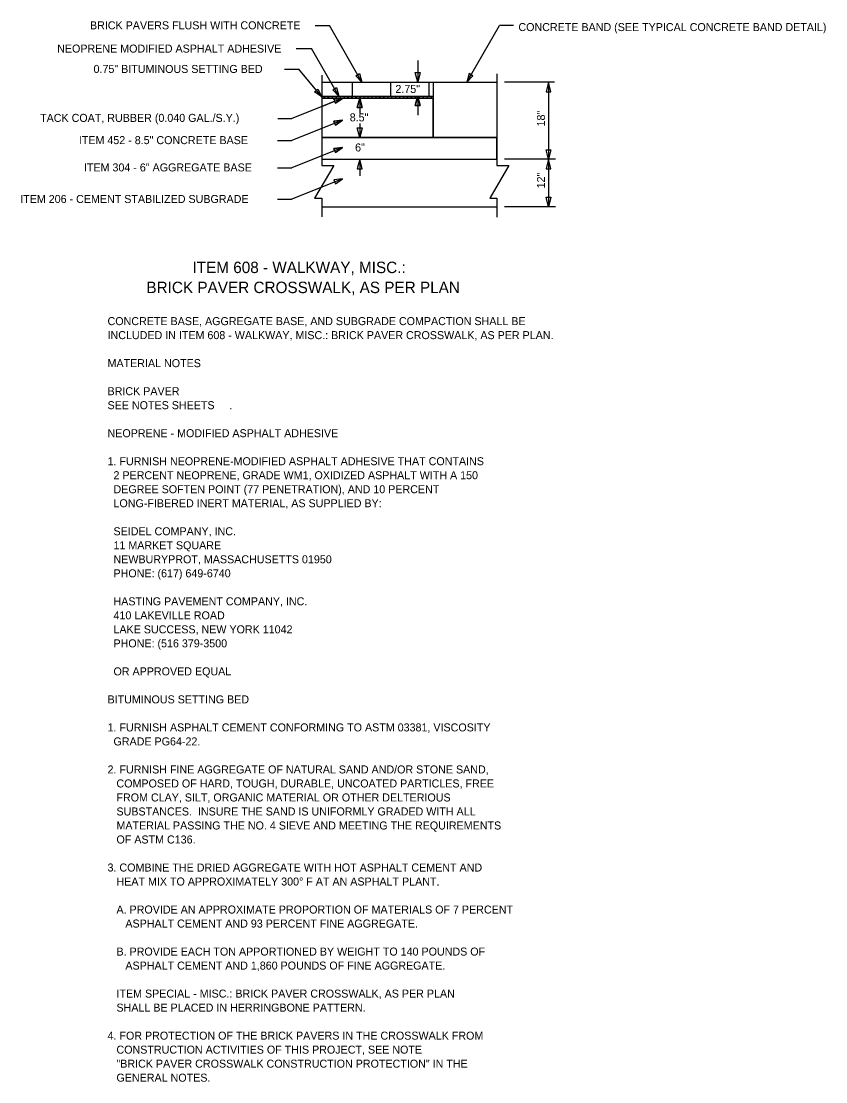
# Model space of a CAD drawing. Extents: x -848 to 1, y -1131 to -115.
# Drawn here: x -837 to -696.2, y -1110.8 to -925.3 of the extents above; entities that cross this region are included whole.
import ezdxf

# ---------------------------------------------------------------- set-up
doc = ezdxf.new("R2010")
doc.units = 0
for name, color, linetype in [('SH_Data', 7, 'Continuous'), ('SH_Text', 7, 'Continuous'), ('TX_X_5', 7, 'Continuous')]:
    doc.layers.add(name, color=color, linetype=linetype)

msp = doc.modelspace()

# ---------------------------------------------------------------- linework, layer by layer
at = {"layer": 'SH_Data'}
for p, q in [((-784.43, -935.97), (-753.78, -935.97)), ((-779.12, -935.97), (-779.12, -938.41)), ((-772.41, -935.97), (-772.41, -938.41)), ((-765.7, -935.97), (-765.7, -938.41)), ((-764.95, -935.97), (-764.95, -945.65)), ((-784.43, -938.41), (-764.95, -938.41)), ((-784.43, -938.76), (-764.95, -938.76)), ((-784.43, -938.76), (-784.43, -940.23)), ((-782.15, -939.32), (-784.43, -940.23)), ((-784.43, -940.23), (-782.15, -939.32)), ((-784.43, -940.23), (-784.43, -944.07)), ((-782.01, -939.67), (-782.15, -939.32)), ((-780.76, -938.76), (-782.01, -939.67)), ((-780.59, -938.76), (-780.76, -938.76)), ((-777.82, -938.76), (-778.51, -938.76)), ((-778.21, -940.44), (-777.79, -938.76)), ((-777.79, -938.76), (-777.82, -938.76)), ((-777.13, -938.76), (-777.79, -938.76)), ((-776.44, -938.76), (-777.13, -938.76)), ((-770.9, -938.76), (-771.59, -938.76)), ((-770.21, -938.76), (-770.9, -938.76)), ((-769.52, -938.76), (-770.21, -938.76)), ((-767.44, -938.76), (-767.55, -938.76)), ((-766.75, -938.76), (-767.44, -938.76)), ((-766.06, -938.76), (-766.75, -938.76)), ((-764.95, -945.65), (-764.95, -938.76)), ((-782.17, -943.17), (-782.31, -942.82)), ((-782.03, -943.52), (-782.17, -943.17)), ((-777.79, -945.65), (-778.21, -943.97)), ((-778.21, -943.97), (-777.79, -943.97)), ((-777.79, -943.97), (-777.37, -943.97)), ((-777.37, -943.97), (-777.79, -945.65)), ((-784.43, -944.07), (-784.43, -945.65)), ((-784.43, -945.65), (-753.78, -945.65)), ((-777.79, -945.65), (-784.43, -945.65)), ((-784.43, -945.65), (-784.43, -948.86)), ((-784.43, -945.65), (-777.79, -945.65)), ((-764.95, -945.65), (-777.79, -945.65)), ((-777.79, -945.65), (-764.95, -945.65)), ((-753.78, -945.65), (-764.95, -945.65)), ((-753.78, -949.47), (-753.78, -945.65)), ((-784.43, -948.86), (-784.43, -949.47)), ((-784.43, -949.47), (-753.78, -949.47)), ((-784.43, -957.77), (-753.78, -957.77))]:
    msp.add_line(p, q, dxfattribs=at)
for points in [[(-784.43, -934.75), (-784.43, -950.56), (-782.33, -950.56), (-785.71, -956.27), (-784.43, -956.27), (-784.43, -959.51)], [(-784.43, -934.75), (-784.43, -950.56), (-782.33, -950.56), (-785.71, -956.27), (-784.43, -956.27), (-784.43, -959.51)], [(-753.78, -934.53), (-753.78, -950.56), (-751.68, -950.56), (-755.05, -956.27), (-753.78, -956.27), (-753.78, -959.6)], [(-780.76, -938.76), (-781.28, -938.76), (-781.97, -938.76), (-782.66, -938.76), (-783.35, -938.76), (-784.05, -938.76), (-784.43, -938.76)], [(-782.15, -939.32), (-782.29, -938.97), (-780.76, -938.76)], [(-778.51, -938.76), (-779.2, -938.76), (-779.9, -938.76), (-780.59, -938.76)], [(-777.79, -938.76), (-777.37, -940.44), (-777.79, -940.44), (-778.21, -940.44)], [(-775.05, -938.76), (-775.75, -938.76), (-776.44, -938.76)], [(-772.98, -938.76), (-773.67, -938.76), (-774.36, -938.76), (-775.05, -938.76)], [(-771.59, -938.76), (-772.29, -938.76), (-772.98, -938.76)], [(-767.72, -938.76), (-768.14, -938.76), (-768.83, -938.76), (-769.52, -938.76)], [(-767.55, -938.76), (-767.22, -940.09), (-767.64, -940.09), (-768.06, -940.09), (-767.72, -938.76)], [(-764.95, -938.76), (-765.37, -938.76), (-766.06, -938.76)], [(-782.31, -942.82), (-780.78, -942.61), (-782.03, -943.52)], [(-782.31, -947.61), (-780.78, -947.4), (-782.03, -948.3), (-782.17, -947.96), (-782.31, -947.61)], [(-784.43, -949.47), (-777.79, -949.47), (-753.78, -949.47)]]:
    msp.add_lwpolyline(points, dxfattribs=at)
at = {"layer": 'SH_Text'}
for p, q in [((-767.64, -932.21), (-767.64, -935.97)), ((-743.69, -935.97), (-752.45, -935.97)), ((-744.76, -935.97), (-744.76, -957.77)), ((-767.64, -938.41), (-767.64, -941.77)), ((-777.79, -938.76), (-777.79, -941.44)), ((-777.79, -943.2), (-777.79, -945.65)), ((-777.79, -949.47), (-777.79, -952.34)), ((-743.51, -949.47), (-752.45, -949.47)), ((-743.51, -957.77), (-752.45, -957.77))]:
    msp.add_line(p, q, dxfattribs=at)
for points in [[(-767.22, -934.29), (-767.64, -935.97), (-768.06, -934.29)], [(-744.34, -937.65), (-744.76, -935.97), (-745.18, -937.65)], [(-767.22, -940.09), (-767.64, -938.41), (-768.06, -940.09)], [(-777.37, -940.44), (-777.79, -938.76), (-778.21, -940.44)], [(-777.37, -943.97), (-777.79, -945.65), (-778.21, -943.97)], [(-777.37, -951.15), (-777.79, -949.47), (-778.21, -951.15)], [(-744.34, -947.79), (-744.76, -949.47), (-745.18, -947.79)], [(-744.34, -951.15), (-744.76, -949.47), (-745.18, -951.15)], [(-744.34, -956.09), (-744.76, -957.77), (-745.18, -956.09)]]:
    msp.add_lwpolyline(points, close=True, dxfattribs=at)
at = {"layer": 'TX_X_5'}
for p, q in [((-785.57, -926.05), (-783.09, -926.05)), ((-777.4, -935.97), (-783.09, -926.05)), ((-759.04, -935.97), (-753.35, -926.05)), ((-750.87, -926.05), (-753.35, -926.05)), ((-788.92, -930.1), (-786.2, -930.1)), ((-781.43, -938.41), (-786.2, -930.1)), ((-790.96, -933.73), (-788.46, -933.73)), ((-784.43, -938.57), (-788.46, -933.73)), ((-784.05, -938.76), (-783.84, -938.41)), ((-783.35, -938.76), (-783.15, -938.41)), ((-782.66, -938.76), (-782.46, -938.41)), ((-781.97, -938.76), (-781.77, -938.41)), ((-781.28, -938.76), (-781.08, -938.41)), ((-780.59, -938.76), (-780.39, -938.41)), ((-779.9, -938.76), (-779.69, -938.41)), ((-779.2, -938.76), (-779, -938.41)), ((-778.51, -938.76), (-778.31, -938.41)), ((-777.82, -938.76), (-777.62, -938.41)), ((-777.13, -938.76), (-776.93, -938.41)), ((-776.44, -938.76), (-776.23, -938.41)), ((-775.75, -938.76), (-775.54, -938.41)), ((-775.05, -938.76), (-774.85, -938.41)), ((-774.36, -938.76), (-774.16, -938.41)), ((-773.67, -938.76), (-773.47, -938.41)), ((-772.98, -938.76), (-772.78, -938.41)), ((-772.29, -938.76), (-772.08, -938.41)), ((-771.59, -938.76), (-771.39, -938.41)), ((-770.9, -938.76), (-770.7, -938.41)), ((-770.21, -938.76), (-770.01, -938.41)), ((-769.52, -938.76), (-769.32, -938.41)), ((-768.83, -938.76), (-768.63, -938.41)), ((-768.14, -938.76), (-767.93, -938.41)), ((-767.44, -938.76), (-767.24, -938.41)), ((-766.75, -938.76), (-766.55, -938.41)), ((-766.06, -938.76), (-765.86, -938.41)), ((-765.37, -938.76), (-765.17, -938.41)), ((-780.76, -938.76), (-789.66, -942.32)), ((-792.13, -942.32), (-789.66, -942.32)), ((-780.78, -942.61), (-789.68, -946.17)), ((-792.15, -946.17), (-789.68, -946.17)), ((-780.78, -947.4), (-789.68, -950.96)), ((-792.15, -950.96), (-789.68, -950.96)), ((-780.78, -952.88), (-789.68, -956.44)), ((-792.15, -956.44), (-789.68, -956.44))]:
    msp.add_line(p, q, dxfattribs=at)
for points in [[(-777.82, -934.48), (-777.4, -935.97), (-778.47, -934.85)], [(-758.62, -934.48), (-759.04, -935.97), (-757.97, -934.85)], [(-785.1, -937.18), (-784.43, -938.57), (-785.68, -937.66)], [(-781.85, -936.92), (-781.43, -938.41), (-782.5, -937.3)], [(-782.01, -939.67), (-780.76, -938.76), (-782.29, -938.97)], [(-782.03, -943.52), (-780.78, -942.61), (-782.31, -942.82)], [(-782.03, -948.3), (-780.78, -947.4), (-782.31, -947.61)], [(-782.03, -953.78), (-780.78, -952.88), (-782.31, -953.09)]]:
    msp.add_lwpolyline(points, close=True, dxfattribs=at)

# ---------------------------------------------------------------- texts
at = {"layer": 'SH_Text'}
for s, rotation, p in [('2.75"', 360, (-771.54, -937.87)), ('8.5"', 360, (-779.53, -942.84)), ('18"', 90, (-745.37, -943.73)), ('6"', 360, (-778.59, -948.1)), ('12"', 90, (-745.37, -954.56))]:
    msp.add_text(s, height=1.4, rotation=rotation, dxfattribs=at).set_placement(p)
for s, height, p in [('ITEM 608 - WALKWAY, MISC.:', 2, (-807.04, -969.37)), ('BRICK PAVER CROSSWALK, AS PER PLAN', 2, (-815.1, -972.87)), ('CONCRETE BASE, AGGREGATE BASE, AND SUBGRADE COMPACTION SHALL BE', 1.4, (-821.9, -978.47)), ('INCLUDED IN ITEM 608 - WALKWAY, MISC.: BRICK PAVER CROSSWALK, AS PER PLAN.', 1.4, (-821.9, -980.92)), ('MATERIAL NOTES', 1.4, (-821.9, -985.82)), ('BRICK PAVER', 1.4, (-821.9, -990.72)), ('SEE NOTES SHEETS     .', 1.4, (-821.9, -993.17)), ('NEOPRENE - MODIFIED ASPHALT ADHESIVE', 1.4, (-821.9, -998.07)), ('1. FURNISH NEOPRENE-MODIFIED ASPHALT ADHESIVE THAT CONTAINS', 1.4, (-821.9, -1002.97)), ('  2 PERCENT NEOPRENE, GRADE WM1, OXIDIZED ASPHALT WITH A 150 ', 1.4, (-821.9, -1005.42)), ('  DEGREE SOFTEN POINT (77 PENETRATION), AND 10 PERCENT ', 1.4, (-821.9, -1007.87)), ('  LONG-FIBERED INERT MATERIAL, AS SUPPLIED BY:', 1.4, (-821.9, -1010.32)), ('  SEIDEL COMPANY, INC.', 1.4, (-821.9, -1015.22)), ('  11 MARKET SQUARE', 1.4, (-821.9, -1017.67)), ('  NEWBURYPROT, MASSACHUSETTS 01950', 1.4, (-821.9, -1020.12)), ('  PHONE: (617) 649-6740', 1.4, (-821.9, -1022.57)), ('  HASTING PAVEMENT COMPANY, INC.', 1.4, (-821.9, -1027.47)), ('  410 LAKEVILLE ROAD', 1.4, (-821.9, -1029.92)), ('  LAKE SUCCESS, NEW YORK 11042', 1.4, (-821.9, -1032.37)), ('  PHONE: (516 379-3500', 1.4, (-821.9, -1034.82)), ('  OR APPROVED EQUAL', 1.4, (-821.9, -1039.72)), ('BITUMINOUS SETTING BED', 1.4, (-821.9, -1044.62)), ('1. FURNISH ASPHALT CEMENT CONFORMING TO ASTM 03381, VISCOSITY', 1.4, (-821.9, -1049.52)), ('  GRADE PG64-22.', 1.4, (-821.9, -1051.97)), ('2. FURNISH FINE AGGREGATE OF NATURAL SAND AND/OR STONE SAND,', 1.4, (-821.9, -1056.87)), ('   COMPOSED OF HARD, TOUGH, DURABLE, UNCOATED PARTICLES, FREE', 1.4, (-821.9, -1059.32)), ('   FROM CLAY, SILT, ORGANIC MATERIAL OR OTHER DELTERIOUS', 1.4, (-821.9, -1061.77)), ('   SUBSTANCES.  INSURE THE SAND IS UNIFORMLY GRADED WITH ALL', 1.4, (-821.9, -1064.22)), ('   MATERIAL PASSING THE NO. 4 SIEVE AND MEETING THE REQUIREMENTS', 1.4, (-821.9, -1066.67)), ('   OF ASTM C136.', 1.4, (-821.9, -1069.12)), ('3. COMBINE THE DRIED AGGREGATE WITH HOT ASPHALT CEMENT AND', 1.4, (-821.9, -1074.02)), ('   HEAT MIX TO APPROXIMATELY 300%%D F AT AN ASPHALT PLANT.', 1.4, (-821.9, -1076.47)), ('   A. PROVIDE AN APPROXIMATE PROPORTION OF MATERIALS OF 7 PERCENT', 1.4, (-821.9, -1081.37)), ('      ASPHALT CEMENT AND 93 PERCENT FINE AGGREGATE.', 1.4, (-821.9, -1083.82)), ('   B. PROVIDE EACH TON APPORTIONED BY WEIGHT TO 140 POUNDS OF', 1.4, (-821.9, -1088.72)), ('      ASPHALT CEMENT AND 1,860 POUNDS OF FINE AGGREGATE.', 1.4, (-821.9, -1091.17)), ('   ITEM SPECIAL - MISC.: BRICK PAVER CROSSWALK, AS PER PLAN', 1.4, (-821.9, -1096.07)), ('   SHALL BE PLACED IN HERRINGBONE PATTERN.', 1.4, (-821.9, -1098.52)), ('4. FOR PROTECTION OF THE BRICK PAVERS IN THE CROSSWALK FROM', 1.4, (-821.9, -1103.42)), ('   CONSTRUCTION ACTIVITIES OF THIS PROJECT, SEE NOTE', 1.4, (-821.9, -1105.87)), ('   "BRICK PAVER CROSSWALK CONSTRUCTION PROTECTION" IN THE ', 1.4, (-821.9, -1108.32)), ('   GENERAL NOTES.', 1.4, (-821.9, -1110.77))]:
    msp.add_text(s, height=height, dxfattribs=at).set_placement(p)
at = {"layer": 'TX_X_5'}
for s, p in [('BRICK PAVERS FLUSH WITH CONCRETE', (-824.97, -926.74)), ('CONCRETE BAND (SEE TYPICAL CONCRETE BAND DETAIL)', (-750.02, -927.05)), ('NEOPRENE MODIFIED ASPHALT ADHESIVE', (-830.71, -930.81)), ('0.75" BITUMINOUS SETTING BED', (-824.35, -934.37)), ('TACK COAT, RUBBER (0.040 GAL./S.Y.)', (-833.7, -942.93)), ('ITEM 452 - 8.5" CONCRETE BASE', (-826.92, -946.82)), ('ITEM 304 - 6" AGGREGATE BASE', (-826.03, -951.59)), ('ITEM 206 - CEMENT STABILIZED SUBGRADE', (-837.18, -957.11))]:
    msp.add_text(s, height=1.4, dxfattribs=at).set_placement(p)

doc.saveas('drawing.dxf')
